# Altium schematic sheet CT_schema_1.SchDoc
size 562 x 511 mm
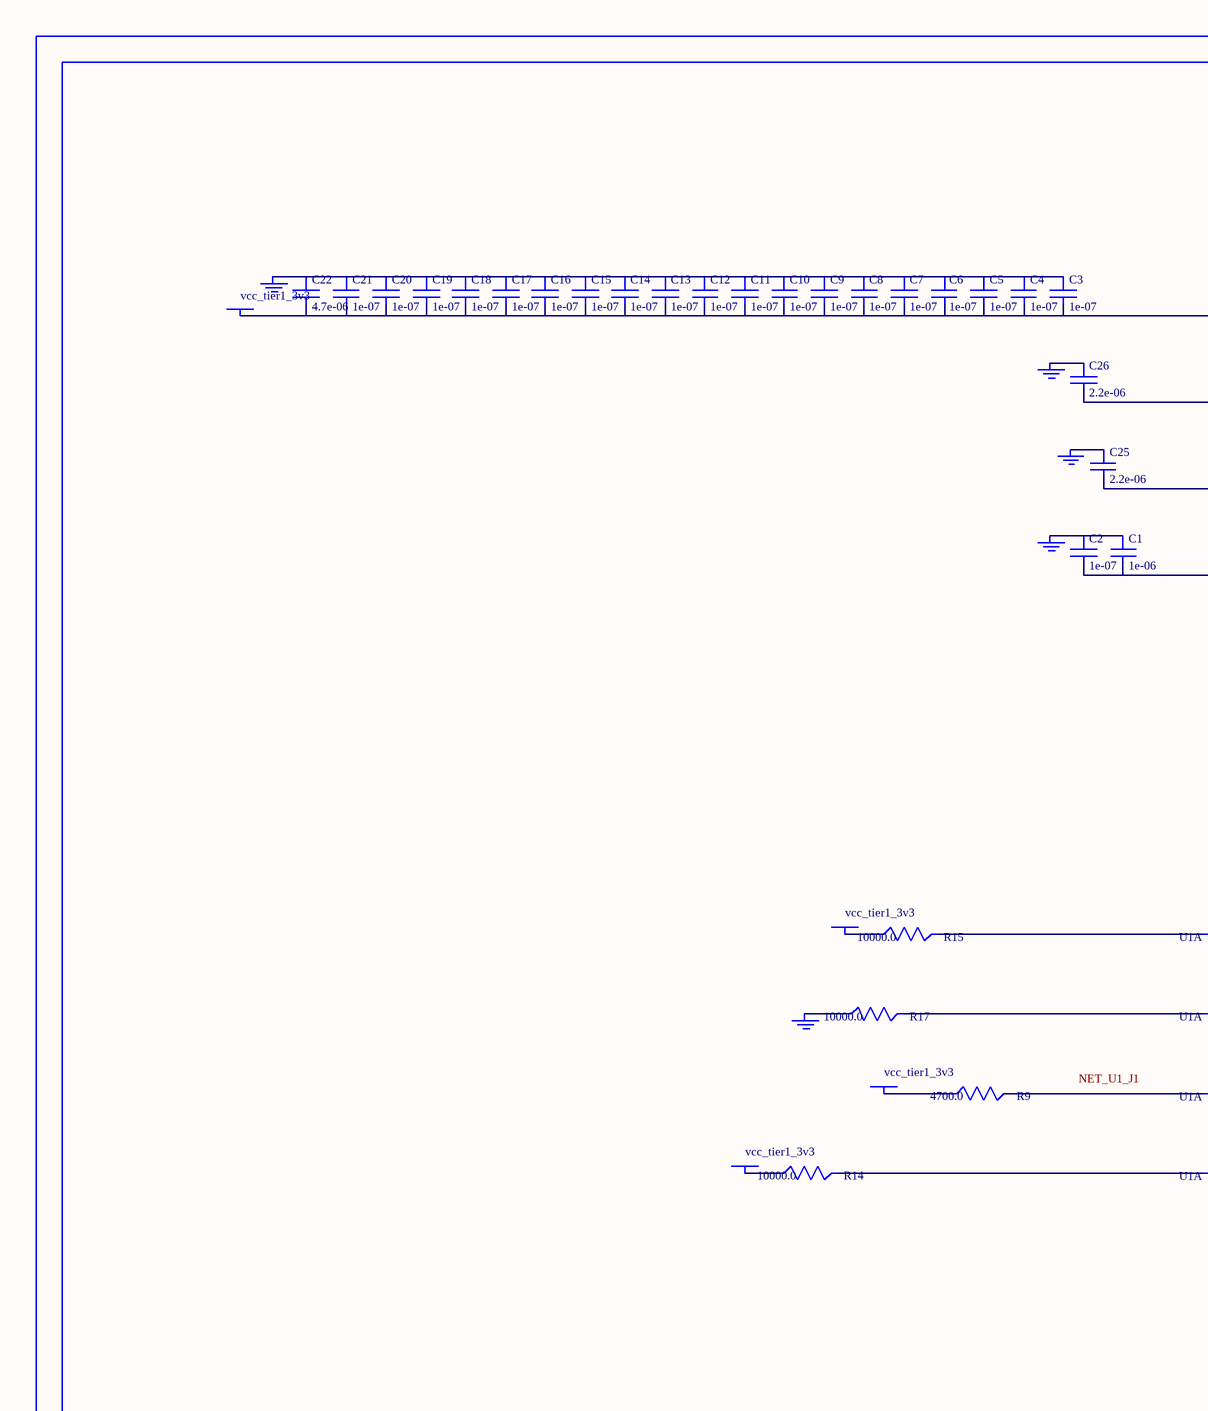
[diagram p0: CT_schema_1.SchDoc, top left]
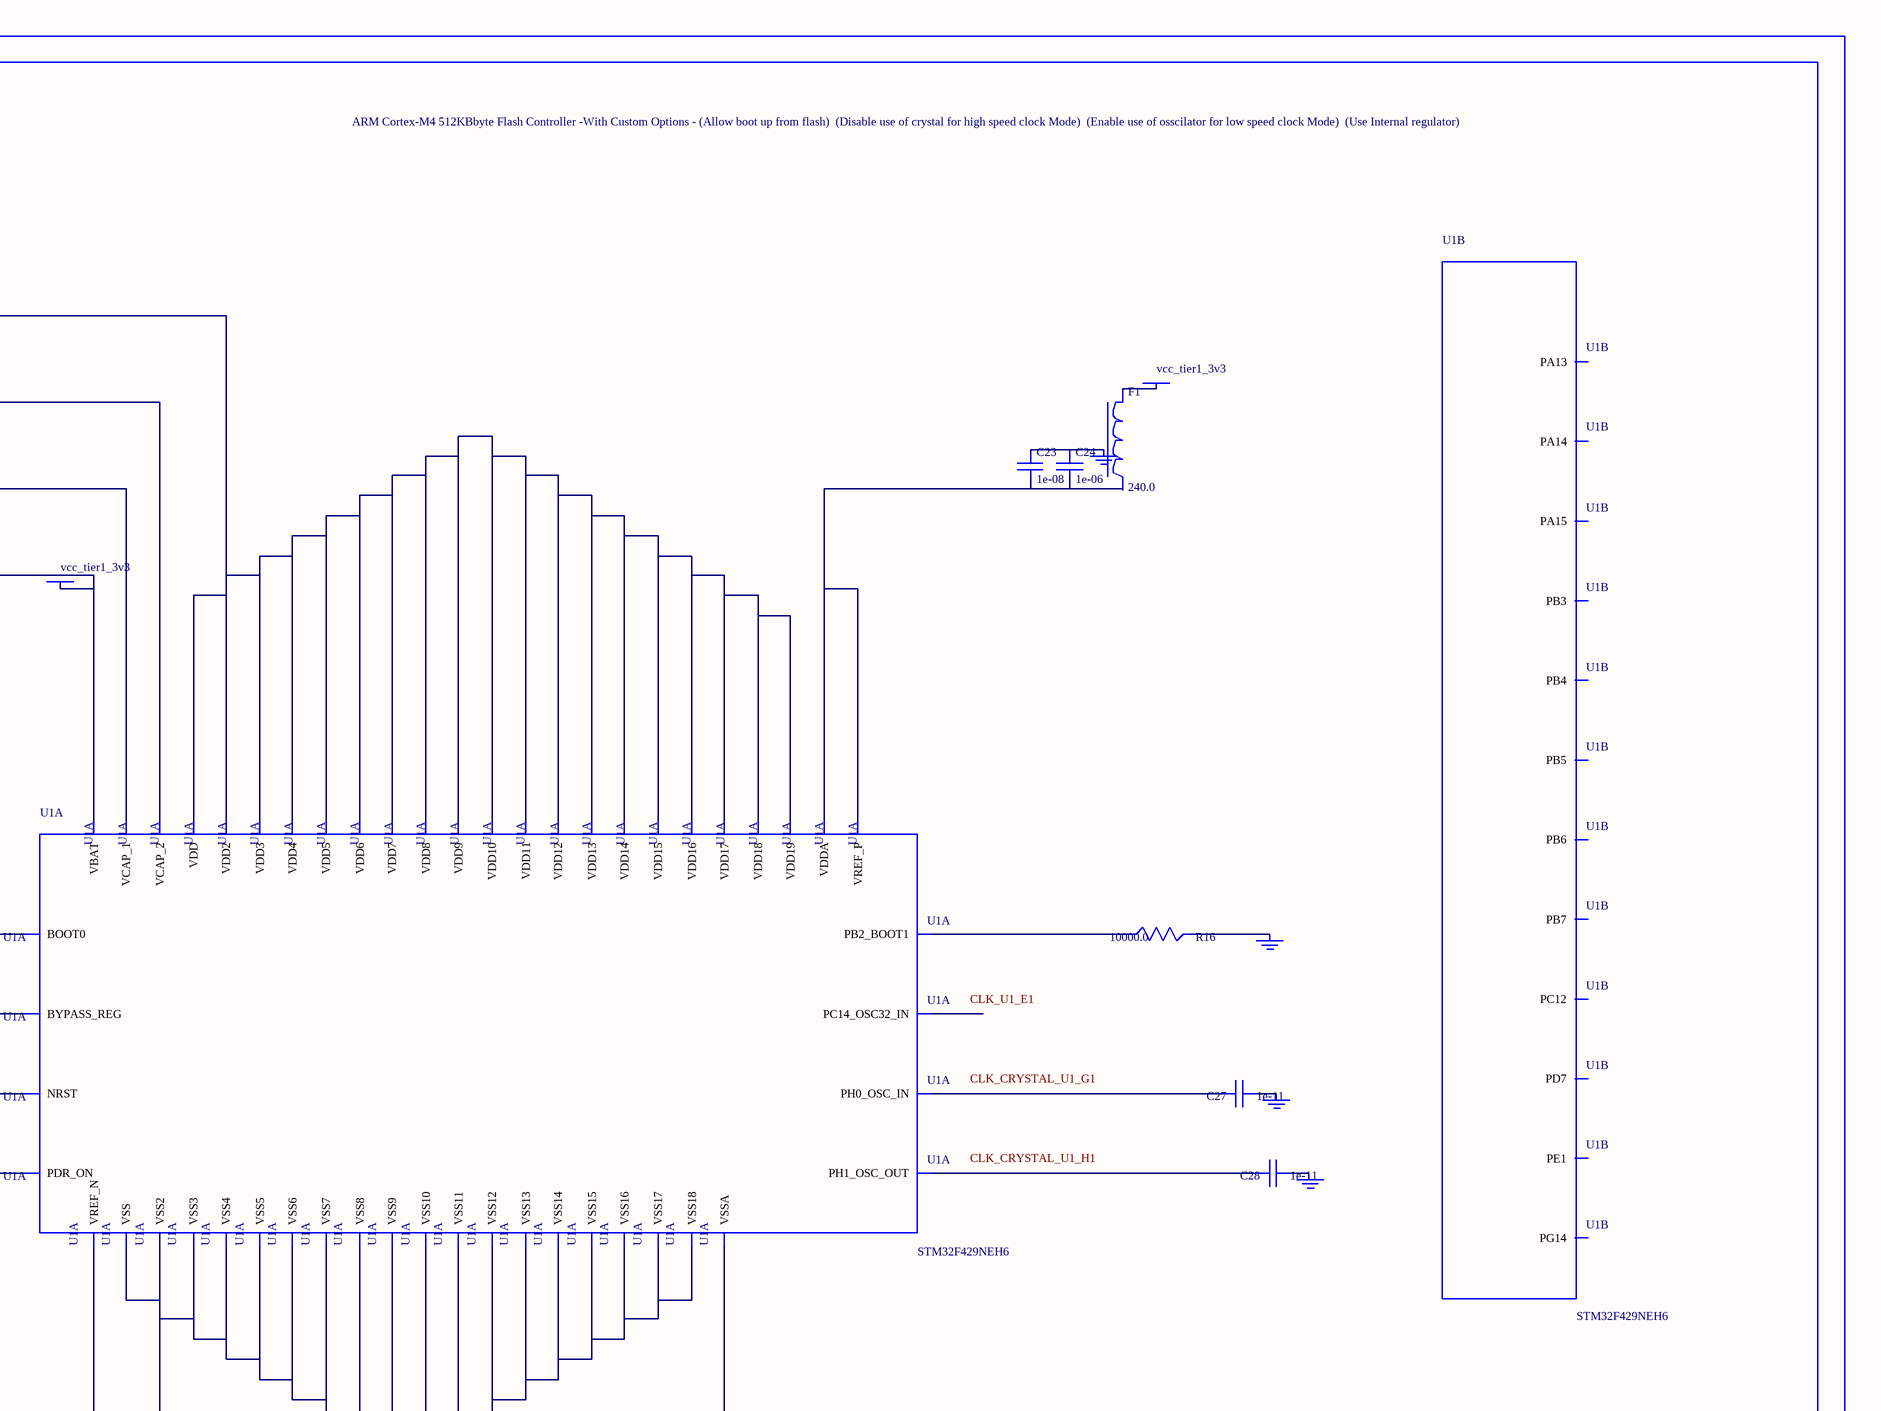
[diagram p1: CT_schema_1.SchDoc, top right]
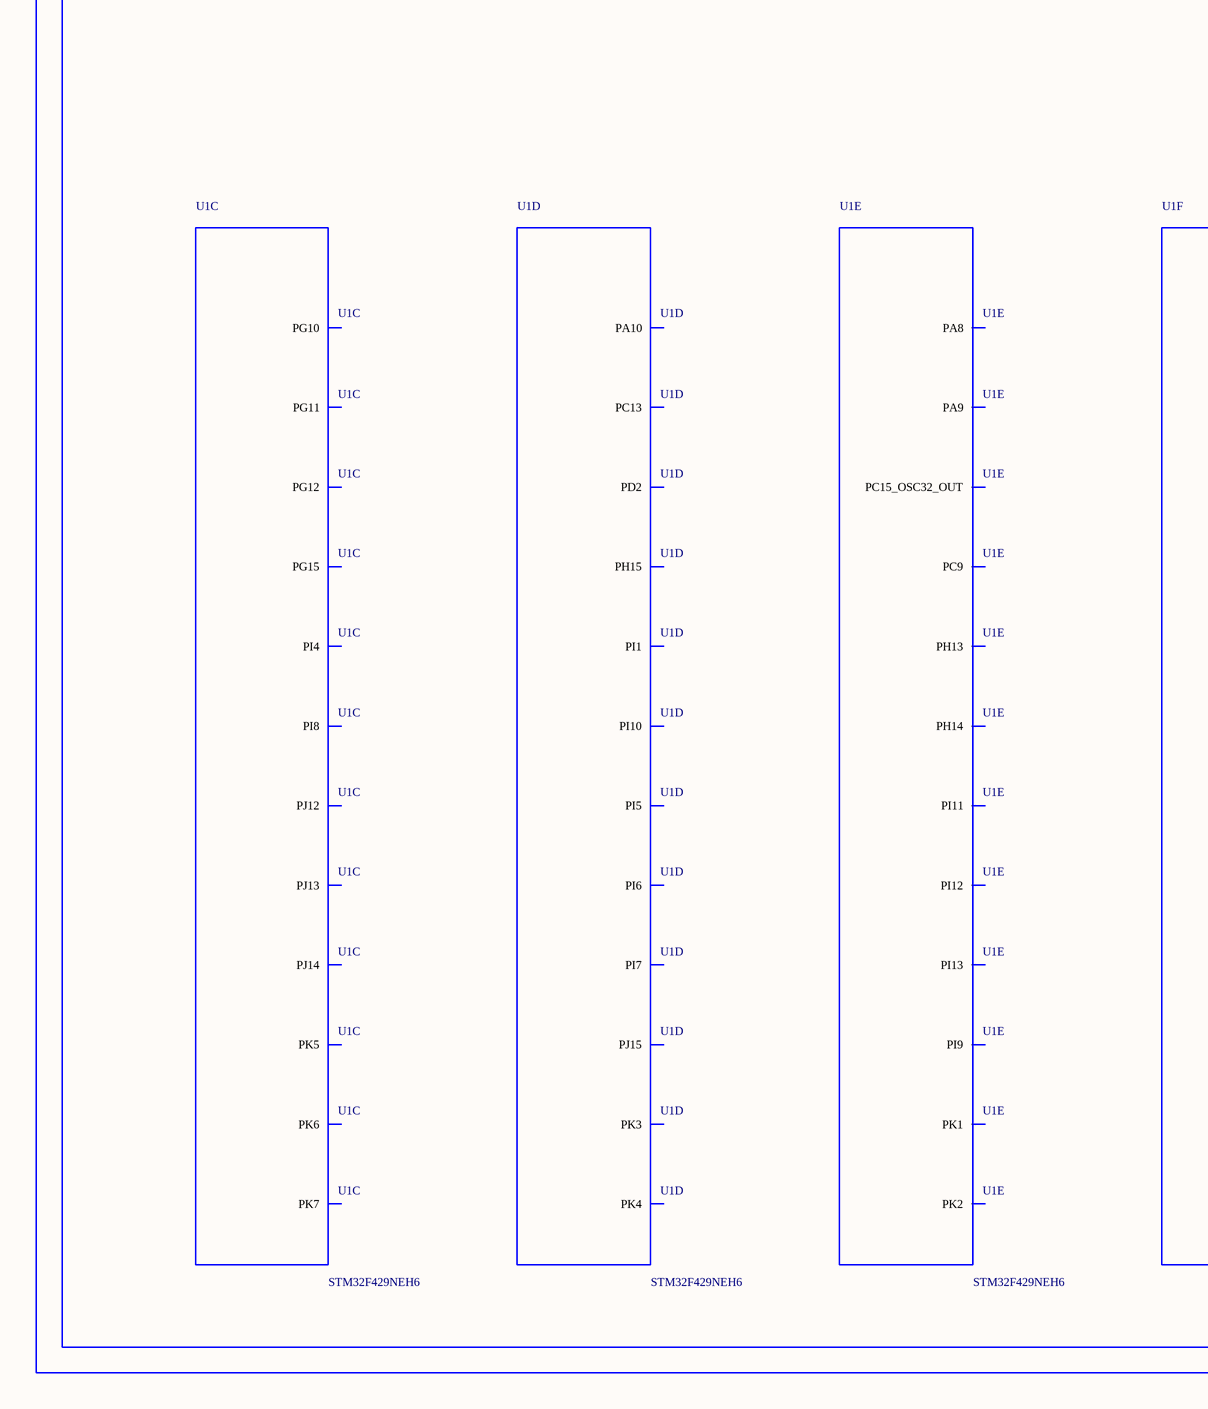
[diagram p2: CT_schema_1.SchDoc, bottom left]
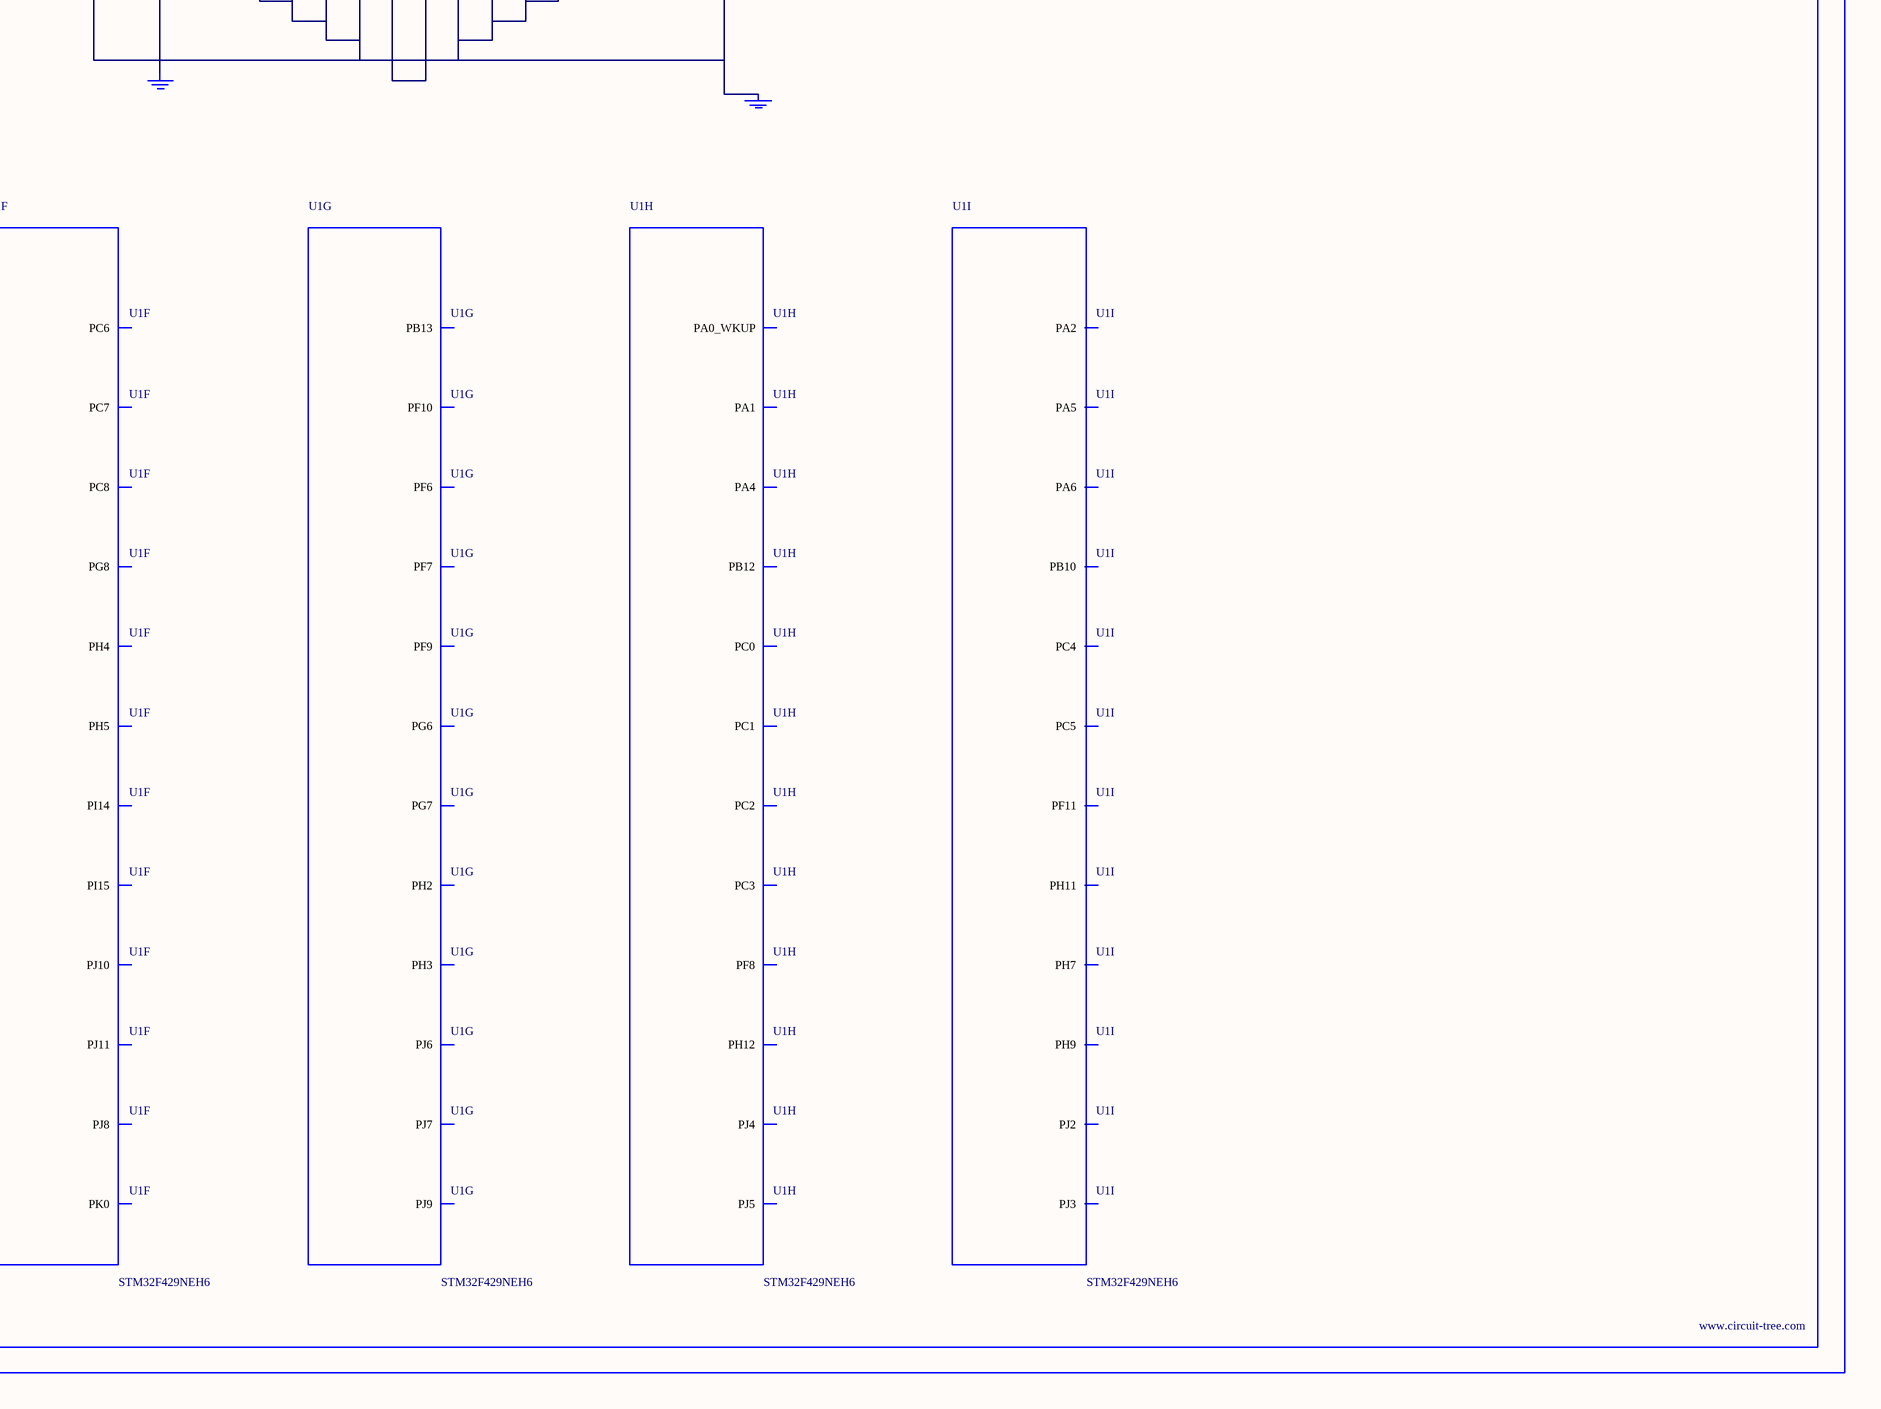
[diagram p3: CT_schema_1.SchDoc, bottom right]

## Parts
BORDER0  (no value)
C1  1e-06  [C0603]
C2  1e-07  [C0603]
C3  1e-07  [C0603]
C4  1e-07  [C0603]
C5  1e-07  [C0603]
C6  1e-07  [C0603]
C7  1e-07  [C0603]
C8  1e-07  [C0603]
C9  1e-07  [C0603]
C10  1e-07  [C0603]
C11  1e-07  [C0603]
C12  1e-07  [C0603]
C13  1e-07  [C0603]
C14  1e-07  [C0603]
C15  1e-07  [C0603]
C16  1e-07  [C0603]
C17  1e-07  [C0603]
C18  1e-07  [C0603]
C19  1e-07  [C0603]
C20  1e-07  [C0603]
C21  1e-07  [C0603]
C22  4.7e-06  [C0603]
C23  1e-08  [C0603]
C24  1e-06  [C0603]
C25  2.2e-06  [C0603]
C26  2.2e-06  [C0603]
C27  1e-11  [C0402]
C28  1e-11  [C0402]
F1  240.0  [L0603]
GND_INSTANCE_0_0  (no value)
GND_INSTANCE_0_1  (no value)
GND_INSTANCE_0_2  (no value)
GND_INSTANCE_0_3  (no value)
GND_INSTANCE_0_4  (no value)
GND_INSTANCE_0_5  (no value)
GND_INSTANCE_0_6  (no value)
GND_INSTANCE_0_7  (no value)
GND_INSTANCE_0_8  (no value)
GND_INSTANCE_0_9  (no value)
GND_INSTANCE_0_10  (no value)
POWER_INSTANCE_0_0  vcc_tier1_3v3
POWER_INSTANCE_0_1  vcc_tier1_3v3
POWER_INSTANCE_0_2  vcc_tier1_3v3
POWER_INSTANCE_0_3  vcc_tier1_3v3
POWER_INSTANCE_0_4  vcc_tier1_3v3
POWER_INSTANCE_0_5  vcc_tier1_3v3
R9  4700.0  [R0603]
R14  10000.0  [R0603]
R15  10000.0  [R0603]
R16  10000.0  [R0603]
R17  10000.0  [R0603]
U1  STM32F429NEH6  [TFBGA216]  (parts A,B,C,D,E,F,G,H,I of 17)

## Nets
NetC1_1: C1.1 C2.1 GND_INSTANCE_0_0.0(GND)
NetC1_2: C1.2 C2.2 POWER_INSTANCE_0_0.0(PWR) U1.C1(VBAT)
NetC3_1: C3.1 C4.1 C5.1 C6.1 C7.1 C8.1 C9.1 C10.1 C11.1 C12.1 C13.1 C14.1 C15.1 C16.1 C17.1 C18.1 C19.1 C20.1 C21.1 C22.1 GND_INSTANCE_0_2.0(GND)
NetC3_2: C3.2 C4.2 C5.2 C6.2 C7.2 C8.2 C9.2 C10.2 C11.2 C12.2 C13.2 C14.2 C15.2 C16.2 C17.2 C18.2 C19.2 C20.2 C21.2 C22.2 POWER_INSTANCE_0_2.0(PWR) U1.E7(VDD2) U1.E8(VDD3) U1.E9(VDD4) U1.E10(VDD) U1.F4(VDD6) U1.F5(VDD7) U1.F11(VDD5) U1.G5(VDD9) U1.G11(VDD8) U1.H5(VDD11) U1.H11(VDD10) U1.J5(VDD13) U1.J11(VDD12) U1.K5(VDD15) U1.K11(VDD14) U1.L7(VDD17) U1.L8(VDD18) U1.L9(VDD19) U1.L10(VDD16)
NetC23_1: C23.1 C24.1 GND_INSTANCE_0_1.0(GND)
NetC23_2: C23.2 C24.2 U1.P1(VREF_P) U1.R1(VDDA)
NetC25_1: C25.1 GND_INSTANCE_0_5.0(GND)
NetC25_2: C25.2 U1.L11(VCAP_1)
NetC26_1: C26.1 GND_INSTANCE_0_6.0(GND)
NetC26_2: C26.2 U1.E11(VCAP_2)
NetC27_1: C27.1 GND_INSTANCE_0_7.0(GND)
NetC27_2: C27.2 U1.G1(PH0_OSC_IN)
NetC28_1: C28.1 GND_INSTANCE_0_8.0(GND)
NetC28_2: C28.2 U1.H1(PH1_OSC_OUT)
NetF1_1: F1.1 POWER_INSTANCE_0_1.0(PWR)
NetGND_INSTANCE_0_3_0: GND_INSTANCE_0_3.0(GND) R16.2
NetGND_INSTANCE_0_4_0: GND_INSTANCE_0_4.0(GND) R17.1
NetGND_INSTANCE_0_9_0: GND_INSTANCE_0_9.0(GND) GND_INSTANCE_0_10.0(GND) U1.F2(VSS2) U1.F6(VSS3) U1.F7(VSS4) U1.F8(VSS5) U1.F9(VSS6) U1.F10(VSS) U1.G6(VSS8) U1.G10(VSS7) U1.H6(VSS10) U1.H10(VSS9) U1.J6(VSS12) U1.J10(VSS11) U1.K6(VSS14) U1.K7(VSS15) U1.K8(VSS16) U1.K9(VSS17) U1.K10(VSS13) U1.L6(VSS18) U1.M1(VSSA) U1.N1(VREF_N)
NetPOWER_INSTANCE_0_3_0: POWER_INSTANCE_0_3.0(PWR) R14.1
NetPOWER_INSTANCE_0_4_0: POWER_INSTANCE_0_4.0(PWR) R15.1
NetPOWER_INSTANCE_0_5_0: POWER_INSTANCE_0_5.0(PWR) R9.1
NetR9_2: R9.2 U1.J1(NRST)
NetR14_2: R14.2 U1.E5(PDR_ON)
NetR15_2: R15.2 U1.E6(BOOT0)
NetR16_1: R16.1 U1.M5(PB2_BOOT1)
NetR17_2: R17.2 U1.L5(BYPASS_REG)

Not connected (* = marked no-connect by the designer): F1 2; U1 A4(PG14) A5(PE1) A8(PB5) A9(PB4) A10(PB3) A11(PD7) A12(PC12) A13(PA15) A14(PA14) A15(PA13) B5(PB7) B6(PB6) B7(PG15) B8(PG11) B9(PJ13) B10(PJ12) C2(PI8) C3(PI4) C4(PK7) C5(PK6) C6(PK5) C7(PG12) C8(PG10) C9(PJ14) D1(PC13) D3(PI5) D4(PI7) D5(PI10) D6(PI6) D7(PK4) D8(PK3) D10(PJ15) D12(PD2) D13(PH15) D14(PI1) D15(PA10) E1(PC14_OSC32_IN) E3(PI12) E4(PI9) E12(PH13) E13(PH14) E15(PA9) F1(PC15_OSC32_OUT) F3(PI11) F12(PK1) F13(PK2) F14(PC9) F15(PA8) G3(PI13) G4(PI15) G12(PJ11) G13(PK0) G14(PC8) G15(PC7) H3(PI14) H4(PH4) H12(PJ8) H13(PJ10) H14(PG8) H15(PC6) J3(PH5) J4(PH3) J12(PJ7) J13(PJ9) J14(PG7) J15(PG6) K1(PF7) K2(PF6) K4(PH2) K12(PJ6) K14(PB13) L1(PF10) L2(PF9) L3(PF8) L4(PC3) L13(PB12) M2(PC0) M3(PC1) M4(PC2) M9(PJ4) M14(PJ5) M15(PH12) N2(PA1) N3(PA0_WKUP) N4(PA4) N5(PC4) N8(PJ3) N13(PH7) N14(PH9) N15(PH11) P2(PA2) P3(PA6) P4(PA5) P5(PC5) P7(PJ2) P8(PF11) P12(PB10)

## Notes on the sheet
- Labels drawn without touching a wire or pin: CLK_CRYSTAL_U1_G1, CLK_CRYSTAL_U1_H1, CLK_U1_E1, NET_U1_J1

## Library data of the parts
BORDER0 = BORDER_PAGE0
C1 C24 = C0603C105K3RACTU
C2-C21 = 06035C104K4Z2A
C22 = GRM188R6YA475KE15D
C23 = 06035C103K4Z2A
C25 C26 = C0603C225K8RACTU
C27 C28 = C0402C100K3GACTU
F1 = Z0603C241ASMST
GND_INSTANCE_0_0-GND_INSTANCE_0_10 = GND
POWER_INSTANCE_0_0-POWER_INSTANCE_0_5 = PWR
R9 = RC0603JR-074K7L
R14-R17 = RC0603JR-0710KL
